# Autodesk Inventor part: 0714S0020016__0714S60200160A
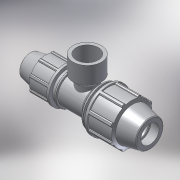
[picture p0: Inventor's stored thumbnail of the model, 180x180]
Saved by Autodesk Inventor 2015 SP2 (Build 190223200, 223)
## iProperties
Created: 2017-02
Part Number: 0714S0020016__0714S60200160A
Material: PVC-Piping
Description: PLASSON REDUCING TEE FEMALE 20-3/4"-16
Document SubType Name: Modeling
Designer: KIM
Mass: 92.6774 g
Surface Area: 199.44 cm^2
Volume: 66.1981 cm^3
Density: 1.4 g/cm^3
Appearance: Smooth - White
Author: KIM
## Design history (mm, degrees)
derived "0714S0.ipt"
feature "Solid1::0714S0.ipt"
feature "Solid2::0714S0.ipt"
tag "TaggingFeature1"
body "Solid1"
body "Solid2"
other parameters: "d4" = 11, "d5" = 18.85714, "d7" = 48, "d9" = 18.85714, "d11" = 1.88571, "d12" = 38.4, "d13" = 120 deg, "d15" = 12 deg, "d16" = 43.2, "d18" = 1, "d19" = 35 deg, "d20" = 17.5 deg, "d21" = 44.64, "d23" = 0, "d25" = 360 deg, "d27" = 0.96, "d42" = 29.04, "d46" = 0.6, "d51" = 132, "d53" = 12 deg, "d54" = 52, "d56" = 24, "d57" = 16, "d58" = 18, "d59" = 14.4, "d60" = 35.1, "d61" = 31.2, "d62" = 16.5, "d63" = 23.76, "d64" = 120 deg, "d65" = 39, "d68" = 9.42857, "d74" = 36.27, "d75" = 35 deg, "d76" = 17.5 deg, "d78" = 0, "d80" = 360 deg, "d85" = 0.78, "d88" = 0.32, "d107" = 2.6, "d108" = 0, "d109" = 2.6, "d110" = 0, "d112" = 3.96, "d113" = 45 deg, "d114" = 24.117, "d115" = 42, "d116" = 19, "d117" = 14.4, "d118" = 31.3521, "d119" = 135 deg, "d120" = 3.61755, "d122" = 69, "d123" = 3.96, "d125" = 0, "d127" = 0, "E_" = 48, "H_" = 132, "l_" = 52, "d_1" = 16, "E_1" = 39, "L_" = 69, "l_2" = 19, "A_" = 42, "Rp_" = 24.117
